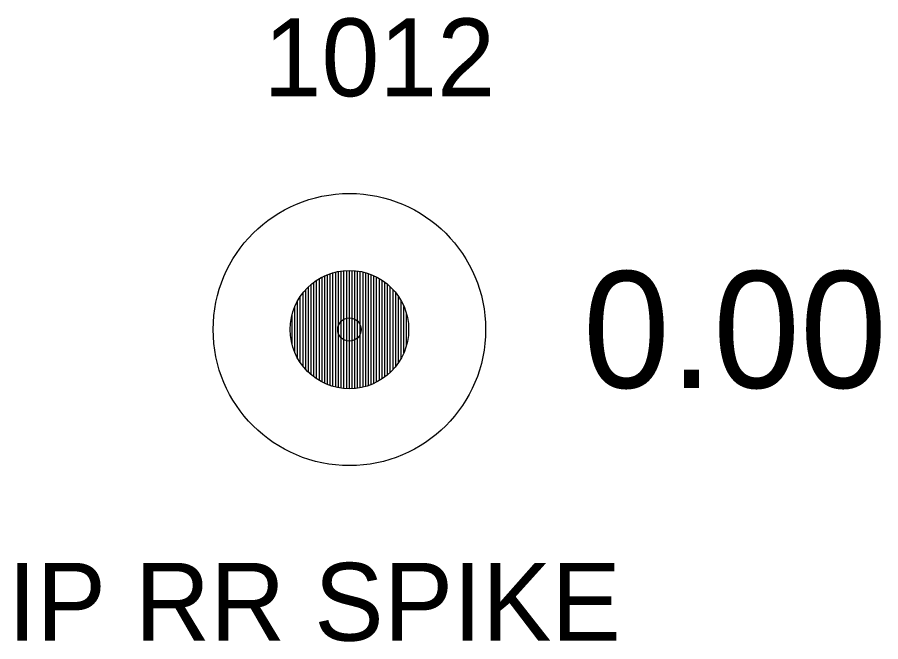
# Model space of a CAD drawing. Extents: x 1448136 to 1453623, y 1125056 to 1128842.
# Drawn here: x 1451192.04 to 1451203.14, y 1128597.54 to 1128605.57 of the extents above; entities that cross this region are included whole.
import ezdxf

# ---------------------------------------------------------------- set-up
doc = ezdxf.new("R2010")
doc.units = 0
for name, color, linetype in [('RD_EX_DV_Prop_txCode', 7, 'Continuous'), ('RD_EX_DV_PropPin', 7, 'Continuous'), ('RD_EX_TX_DV_Prop_ELEV', 7, 'Continuous'), ('RD_SMD_Locator', 7, 'Continuous')]:
    doc.layers.add(name, color=color, linetype=linetype)

msp = doc.modelspace()

# ---------------------------------------------------------------- linework, layer by layer
at = {"layer": 'RD_EX_DV_PropPin'}
for p, q in [((1451195.96, 1128600.878), (1451195.96, 1128602.229)), ((1451195.995, 1128600.861), (1451195.995, 1128602.246)), ((1451196.03, 1128600.846), (1451196.03, 1128602.261)), ((1451196.065, 1128600.833), (1451196.065, 1128602.274)), ((1451196.1, 1128600.822), (1451196.1, 1128602.285)), ((1451196.136, 1128600.813), (1451196.136, 1128602.294)), ((1451196.171, 1128600.805), (1451196.171, 1128602.301)), ((1451196.206, 1128600.8), (1451196.206, 1128602.307)), ((1451196.241, 1128600.796), (1451196.241, 1128602.311)), ((1451196.276, 1128600.793), (1451196.276, 1128602.314)), ((1451196.311, 1128600.792), (1451196.311, 1128602.314)), ((1451196.346, 1128600.793), (1451196.346, 1128602.314)), ((1451196.381, 1128600.796), (1451196.381, 1128602.311)), ((1451196.416, 1128600.8), (1451196.416, 1128602.307)), ((1451196.451, 1128600.805), (1451196.451, 1128602.301)), ((1451196.486, 1128600.813), (1451196.486, 1128602.294)), ((1451196.521, 1128600.822), (1451196.521, 1128602.285)), ((1451196.556, 1128600.833), (1451196.556, 1128602.274)), ((1451196.591, 1128600.846), (1451196.591, 1128602.261)), ((1451196.626, 1128600.861), (1451196.626, 1128602.246)), ((1451196.661, 1128600.878), (1451196.661, 1128602.229)), ((1451195.82, 1128600.971), (1451195.82, 1128602.135)), ((1451195.855, 1128600.943), (1451195.855, 1128602.163)), ((1451195.89, 1128600.919), (1451195.89, 1128602.188)), ((1451195.925, 1128600.897), (1451195.925, 1128602.21)), ((1451196.696, 1128600.897), (1451196.696, 1128602.21)), ((1451196.731, 1128600.919), (1451196.731, 1128602.188)), ((1451196.766, 1128600.943), (1451196.766, 1128602.163)), ((1451196.801, 1128600.971), (1451196.801, 1128602.135)), ((1451195.715, 1128601.079), (1451195.715, 1128602.027)), ((1451195.75, 1128601.038), (1451195.75, 1128602.068)), ((1451195.785, 1128601.003), (1451195.785, 1128602.104)), ((1451196.836, 1128601.003), (1451196.836, 1128602.104)), ((1451196.871, 1128601.038), (1451196.871, 1128602.068)), ((1451196.906, 1128601.079), (1451196.906, 1128602.027)), ((1451195.645, 1128601.184), (1451195.645, 1128601.923)), ((1451195.68, 1128601.127), (1451195.68, 1128601.98)), ((1451196.941, 1128601.127), (1451196.941, 1128601.98)), ((1451196.976, 1128601.184), (1451196.976, 1128601.923)), ((1451195.61, 1128601.255), (1451195.61, 1128601.851)), ((1451197.011, 1128601.255), (1451197.011, 1128601.851)), ((1451195.575, 1128601.357), (1451195.575, 1128601.749)), ((1451197.046, 1128601.357), (1451197.046, 1128601.749))]:
    msp.add_line(p, q, dxfattribs=at)
for radius in [1.75, 0.761]:
    msp.add_circle((1451196.311, 1128601.553), radius, dxfattribs=at)
at = {"layer": 'RD_SMD_Locator'}
msp.add_circle((1451196.311, 1128601.553), 0.15, dxfattribs=at)

# ---------------------------------------------------------------- texts
at = {"layer": 'RD_EX_DV_Prop_txCode'}
for s, p in [('1012', (1451195.208, 1128604.553)), ('IP RR SPIKE', (1451191.921, 1128597.553))]:
    msp.add_text(s, height=1, dxfattribs=at).set_placement(p)
at = {"layer": 'RD_EX_TX_DV_Prop_ELEV'}
msp.add_text('0.00', height=1.5, dxfattribs=at).set_placement((1451199.311, 1128600.803))

doc.saveas('drawing.dxf')
